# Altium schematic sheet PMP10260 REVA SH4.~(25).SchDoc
size 431 x 279 mm; Date: Not shown in title block; ApprovedBy: Not shown in title block; CheckedBy: Not shown in title block; Author: Not shown in title block; CompanyName: Not shown in title block; Engineer: Not shown in title block; Organization: Not shown in title block; Address1: Not shown in title block; Address2: Not shown in title block; Address3: Not shown in title block; Address4: Not shown in title block; DocumentNumber: 4; Revision: Use project parameter SCH_Rev; SheetNumber: 4; SheetTotal: 4; PageSetup: Record=PageOptions|CenterHorizontal=True|CenterVertical=True|PrintScale=1.00|XCorrection=1.00|YCorrection=1.00|PrintKind=0|BorderSize=5000000|LeftOffset=0|BottomOffset=0|Orientation=2|PaperLength=1000|PaperWidth=1000|Scale=100|PaperSource=15|PrintQuality=600|MediaType=1|DitherType=10|PaperKind=Letter|PrintScaleMode=1
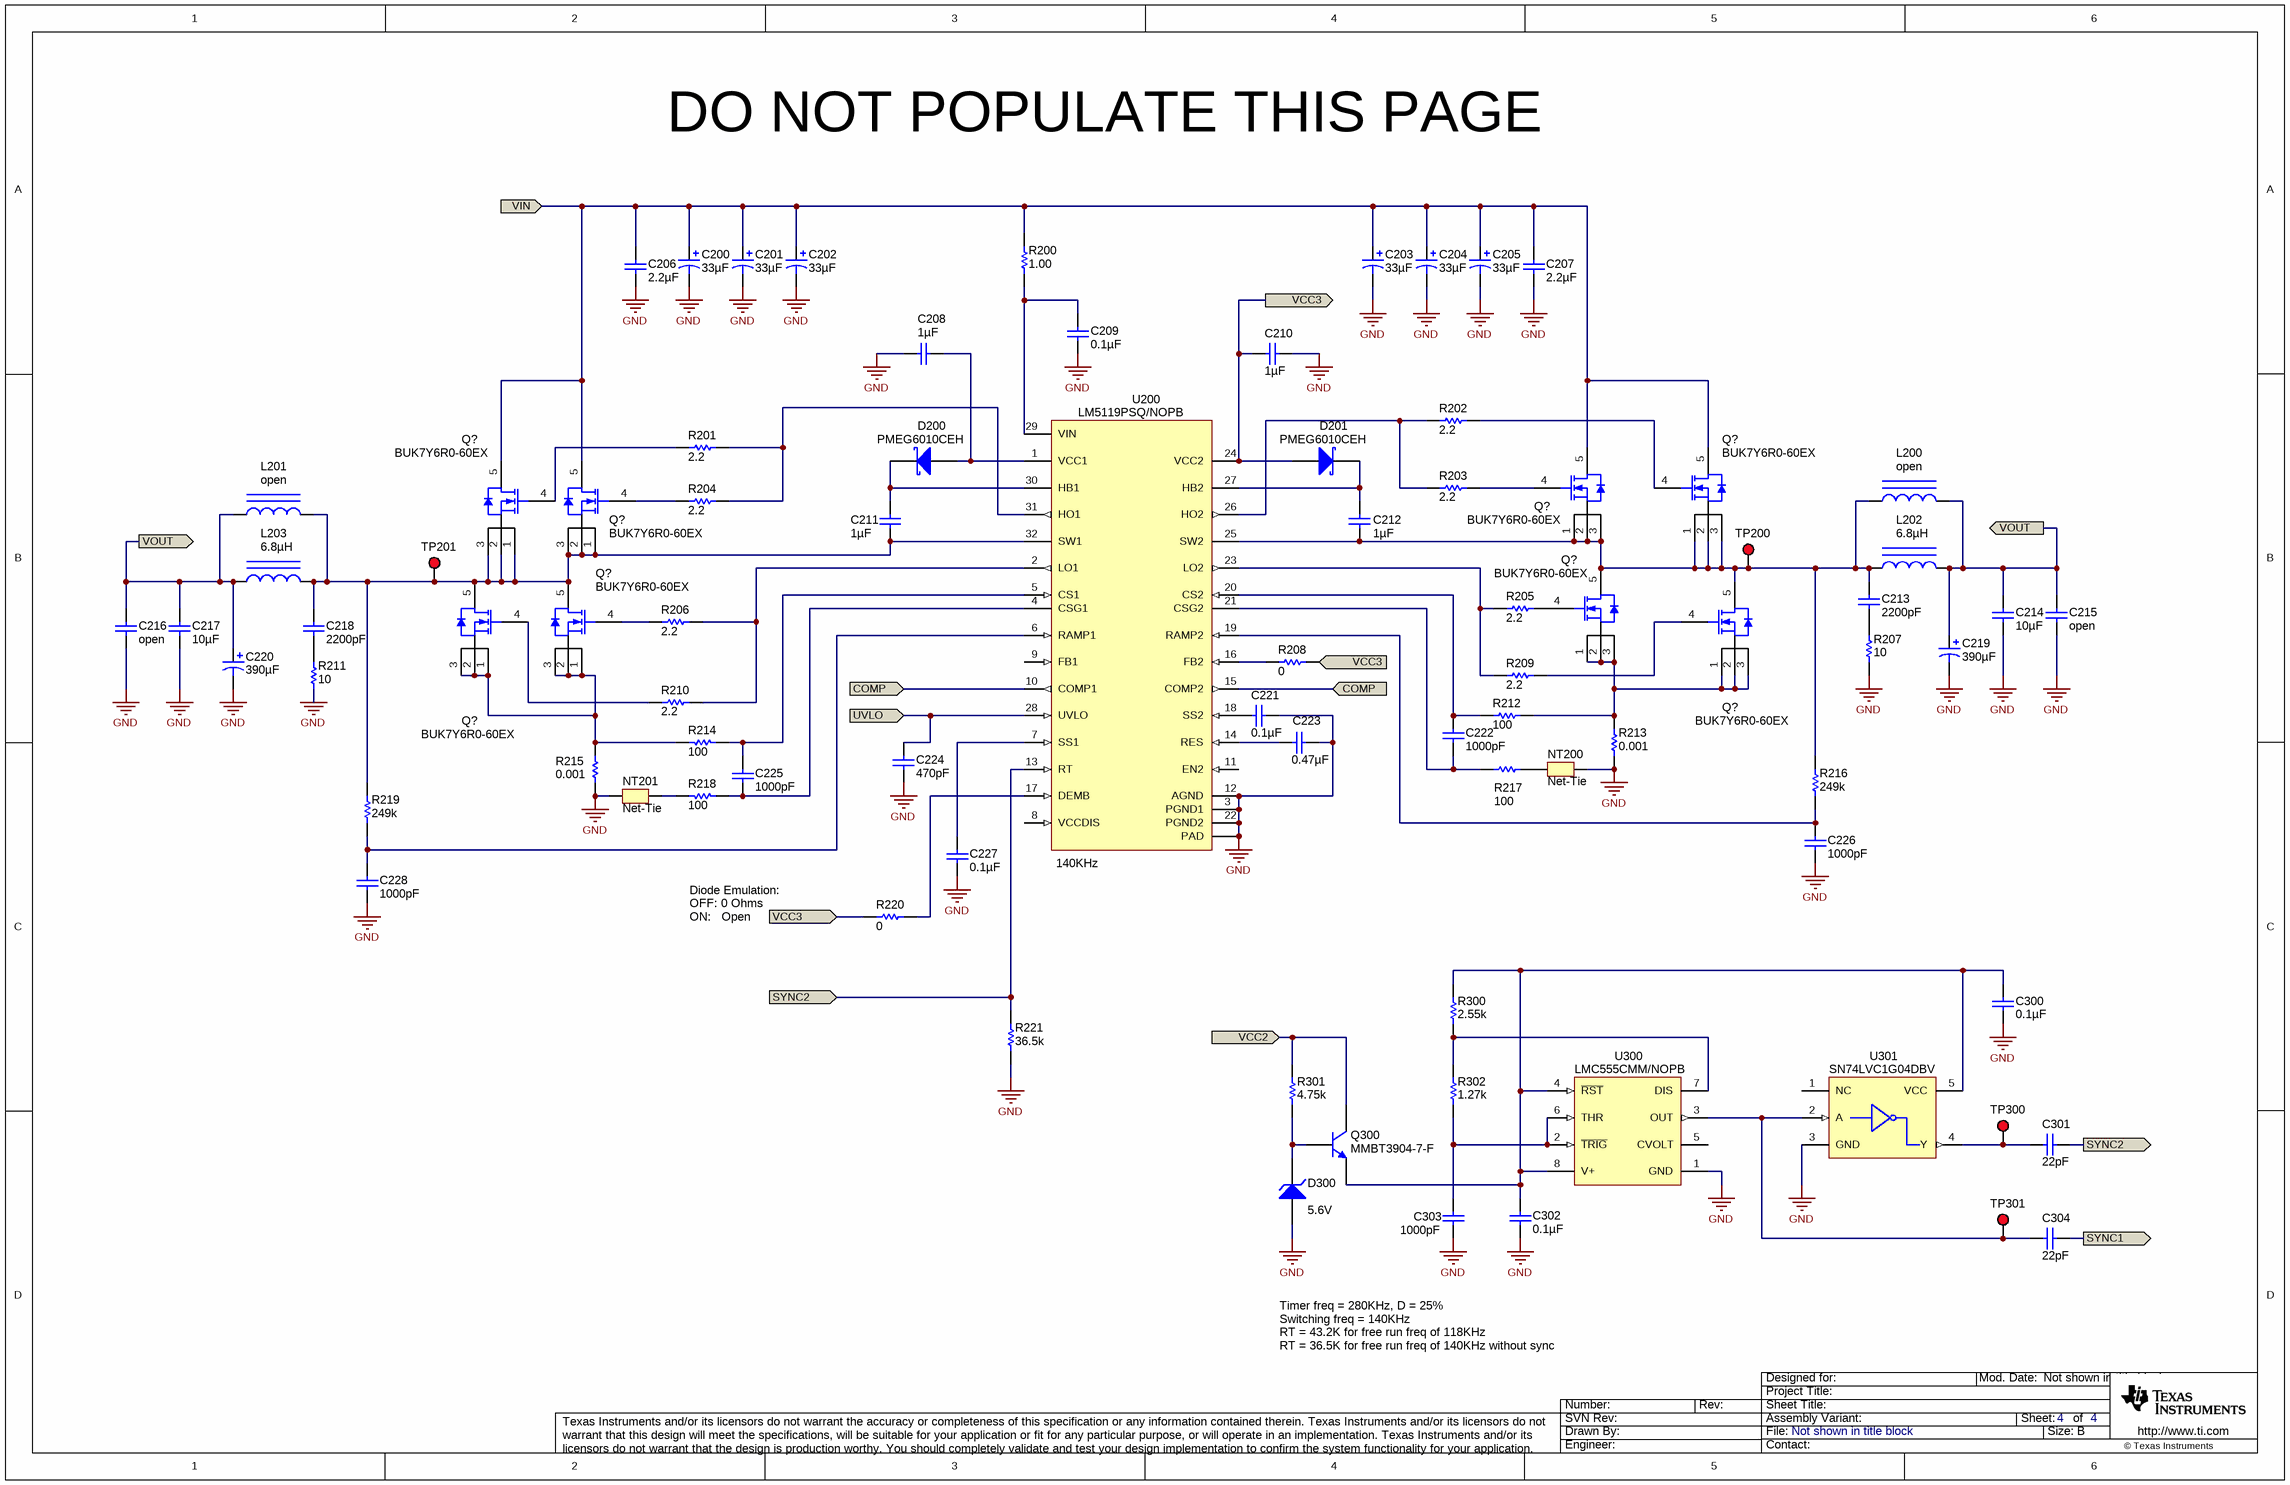
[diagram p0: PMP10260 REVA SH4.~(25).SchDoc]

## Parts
(Parts that share a designator on the sheet are numbered #1, #2 ... from top to bottom, then left to right.)
C200  ValueDisplayed: 33µF  [SXV_E12]  (hidden comment: 63SXV33M)
C201  ValueDisplayed: 33µF  [SXV_E12]  (hidden comment: 63SXV33M)
C202  ValueDisplayed: 33µF  [SXV_E12]  (hidden comment: 63SXV33M)
C203  ValueDisplayed: 33µF  [SXV_E12]  (hidden comment: 63SXV33M)
C204  ValueDisplayed: 33µF  [SXV_E12]  (hidden comment: 63SXV33M)
C205  ValueDisplayed: 33µF  [SXV_E12]  (hidden comment: 63SXV33M)
C206  ValueDisplayed: 2.2µF  [1210]  (hidden comment: GRM32ER72A225KA35L)
C207  ValueDisplayed: 2.2µF  [1210]  (hidden comment: GRM32ER72A225KA35L)
C208  ValueDisplayed: 1µF  [0603L]  (hidden comment: C1608X7R1E105K080AB)
C209  ValueDisplayed: 0.1µF  [0805_HV]  (hidden comment: C2012X7R2A104K)
C210  ValueDisplayed: 1µF  [0603L]  (hidden comment: C1608X7R1E105K080AB)
C211  ValueDisplayed: 1µF  [0603L]  (hidden comment: C1608X7R1E105K080AB)
C212  ValueDisplayed: 1µF  [0603L]  (hidden comment: C1608X7R1E105K080AB)
C213  ValueDisplayed: 2200pF  [0603L]  (hidden comment: C0603C222K5RAC)
C214  ValueDisplayed: 10µF  [1210L]  (hidden comment: GMK325AB7106MM-T)
C215  ValueDisplayed: open  [1210]
C216  ValueDisplayed: open  [1210]
C217  ValueDisplayed: 10µF  [1210L]  (hidden comment: GMK325AB7106MM-T)
C218  ValueDisplayed: 2200pF  [0603L]  (hidden comment: C0603C222K5RAC)
C219  ValueDisplayed: 390µF  [SM_RADIAL_8MM]  (hidden comment: 20SVPF390M)
C220  ValueDisplayed: 390µF  [SM_RADIAL_8MM]  (hidden comment: 20SVPF390M)
C221  ValueDisplayed: 0.1µF  [0603L]  (hidden comment: C1608X7R1H104K)
C222  ValueDisplayed: 1000pF  [0603]  (hidden comment: C1608C0G1H102J)
C223  ValueDisplayed: 0.47µF  [0603L]  (hidden comment: C0603C474K4RACTU)
C224  ValueDisplayed: 470pF  [0603]  (hidden comment: C1608C0G1H471J)
C225  ValueDisplayed: 1000pF  [0603]  (hidden comment: C1608C0G1H102J)
C226  ValueDisplayed: 1000pF  [0603]  (hidden comment: C1608C0G1H102J)
C227  ValueDisplayed: 0.1µF  [0603L]  (hidden comment: C1608X7R1H104K)
C228  ValueDisplayed: 1000pF  [0603]  (hidden comment: C1608C0G1H102J)
C300  ValueDisplayed: 0.1µF  [0805_HV]  (hidden comment: C2012X7R2A104K)
C301  ValueDisplayed: 22pF  [0603]  (hidden comment: C1608C0G1H220J)
C302  ValueDisplayed: 0.1µF  [0805_HV]  (hidden comment: C2012X7R2A104K)
C303  ValueDisplayed: 1000pF  [0603]  (hidden comment: C1608C0G1H102J)
C304  ValueDisplayed: 22pF  [0603]  (hidden comment: C1608C0G1H220J)
D200  PMEG6010CEH  [SOD-123F]
D201  PMEG6010CEH  [SOD-123F]
D300  value 5.6V  [SOD-123]  (hidden comment: MMSZ5232B-7-F)
L200  ValueDisplayed: open  [XAL1510]
L201  ValueDisplayed: open  [XAL1510]
L202  ValueDisplayed: 6.8µH  [SER2915]  (hidden comment: SER2915H-682KL)
L203  ValueDisplayed: 6.8µH  [SER2915]  (hidden comment: SER2915H-682KL)
NT200  Net-Tie  [Net-Tie_10mil]  (net tie, no BOM)
NT201  Net-Tie  [Net-Tie_10mil]  (net tie, no BOM)
Q300  MMBT3904-7-F  [SOT-23]
Q?#1  BUK7Y6R0-60EX  [LFPAK56]
Q?#2  BUK7Y6R0-60EX  [LFPAK56]
Q?#3  BUK7Y6R0-60EX  [LFPAK56]
Q?#4  BUK7Y6R0-60EX  [LFPAK56]
Q?#5  BUK7Y6R0-60EX  [LFPAK56]
Q?#6  BUK7Y6R0-60EX  [LFPAK56]
Q?#7  BUK7Y6R0-60EX  [LFPAK56]
Q?#8  BUK7Y6R0-60EX  [LFPAK56]
R200  value 1.00  [0805_HV]  (hidden comment: CRCW08051R00FKEA)
R201  value 2.2  [0603L]  (hidden comment: CRCW06032R20JNEA)
R202  value 2.2  [0603L]  (hidden comment: CRCW06032R20JNEA)
R203  value 2.2  [0603L]  (hidden comment: CRCW06032R20JNEA)
R204  value 2.2  [0603L]  (hidden comment: CRCW06032R20JNEA)
R205  value 2.2  [0603L]  (hidden comment: CRCW06032R20JNEA)
R206  value 2.2  [0603L]  (hidden comment: CRCW06032R20JNEA)
R207  value 10  [2010M]  (hidden comment: CRCW201010R0JNEFHP)
R208  value 0  [0603L]  (hidden comment: CRCW06030000Z0EA)
R209  value 2.2  [0603L]  (hidden comment: CRCW06032R20JNEA)
R210  value 2.2  [0603L]  (hidden comment: CRCW06032R20JNEA)
R211  value 10  [2010M]  (hidden comment: CRCW201010R0JNEFHP)
R212  value 100  [0603L]  (hidden comment: RC0603FR-07100RL)
R213  value 0.001  [2512M]  (hidden comment: ERJ-M1WTF1M0U)
R214  value 100  [0603L]  (hidden comment: RC0603FR-07100RL)
R215  value 0.001  [2512M]  (hidden comment: ERJ-M1WTF1M0U)
R216  value 249k  [0603]  (hidden comment: CRCW0603249KFKEA)
R217  value 100  [0603L]  (hidden comment: RC0603FR-07100RL)
R218  value 100  [0603L]  (hidden comment: RC0603FR-07100RL)
R219  value 249k  [0603]  (hidden comment: CRCW0603249KFKEA)
R220  value 0  [0603L]  (hidden comment: CRCW06030000Z0EA)
R221  value 36.5k  [0603]  (hidden comment: CRCW060336K5FKEA)
R300  value 2.55k  [0603]  (hidden comment: CRCW06032K55FKEA)
R301  value 4.75k  [0603]  (hidden comment: CRCW06034K75FKEA)
R302  value 1.27k  [0603]  (hidden comment: CRCW06031K27FKEA)
TP200  5010  [Keystone5010]  (value not drawn)
TP201  5010  [Keystone5010]  (value not drawn)
TP300  5010  [Keystone5010]  (value not drawn)
TP301  5010  [Keystone5010]  (value not drawn)
U200  LM5119PSQ/NOPB  [RTV0032A]
U300  LMC555CMM/NOPB  [MUA08A_N]
U301  SN74LVC1G04DBV  [DBV0005A_N]

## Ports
COMP, SYNC1, SYNC2, UVLO, VCC2, VCC3, VIN, VOUT

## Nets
GND: C200.2(-) C201.2(-) C202.2(-) C203.2(-) C204.2(-) C205.2(-) C206.2 C207.2 C208.2 C209.2 C210.2 C214.2 C215.2 C216.2 C217.2 C219.2(-) C220.2(-) C221.1 C223.1 C224.2 C226.2 C227.2 C228.2 C300.2 C302.2 C303.2 D300.2(A) NT200.2 NT201.1 R207.1 R211.1 R213.1 R215.1 R221.1 U200.3(PGND1) U200.12(AGND) U200.22(PGND2) U200.33(PAD) U300.1(GND) U301.3(GND)
COMP: U200.10(COMP1) U200.15(COMP2) ; port COMP
SYNC1: C304.1 ; port SYNC1
SYNC2: C301.1 R221.2 U200.13(RT) ; port SYNC2
UVLO: C224.1 U200.28(UVLO) ; port UVLO
VCC2: Q300.3(C) R301.2 ; port VCC2
VCC3: C210.1 D201.2(A) R208.2 R220.1 U200.24(VCC2) ; port VCC3
VIN: C200.1(+) C201.1(+) C202.1(+) C203.1(+) C204.1(+) C205.1(+) C206.1 C207.1 Q?#1.5(D) Q?#2.5(D) Q?#3.5(D) Q?#4.5(D) R200.1 ; port VIN
VOUT: C214.1 C215.1 C216.1 C217.1 C219.1(+) C220.1(+) L200.2 L201.1 L202.2 L203.1 ; port VOUT
NetC208_1: C208.1 D200.2(A) U200.1(VCC1)
NetC209_1: C209.1 R200.2 U200.29(VIN)
NetC211_1: C211.1 D200.1(K) U200.30(HB1)
NetC211_2: C211.2 C218.1 L201.2 L203.2 Q?#3.1(S) Q?#3.2(S) Q?#3.3(S) Q?#4.1(S) Q?#4.2(S) Q?#4.3(S) Q?#6.5(D) Q?#7.5(D) R219.2 TP201.1 U200.32(SW1)
NetC212_1: C212.1 D201.1(K) U200.27(HB2)
NetC212_2: C212.2 C213.1 L200.1 L202.1 Q?#1.1(S) Q?#1.2(S) Q?#1.3(S) Q?#2.1(S) Q?#2.2(S) Q?#2.3(S) Q?#5.5(D) Q?#8.5(D) R216.2 TP200.1 U200.25(SW2)
NetC213_2: C213.2 R207.2
NetC218_2: C218.2 R211.2
NetC221_2: C221.2 U200.18(SS2)
NetC222_1: C222.1 R212.1 U200.20(CS2)
NetC222_2: C222.2 R217.1 U200.21(CSG2)
NetC223_2: C223.2 U200.14(RES)
NetC225_1: C225.1 R214.1 U200.5(CS1)
NetC225_2: C225.2 R218.1 U200.4(CSG1)
NetC226_1: C226.1 R216.1 U200.19(RAMP2)
NetC227_1: C227.1 U200.7(SS1)
NetC228_1: C228.1 R219.1 U200.6(RAMP1)
NetC300_1: C300.1 C302.1 Q300.2(E) R300.2 U300.4(~{RST}) U300.8(V+) U301.5(VCC)
NetC301_2: C301.2 TP300.1 U301.4(Y)
NetC303_1: C303.1 R302.1 U300.2(~{TRIG}) U300.6(THR)
NetC304_2: C304.2 TP301.1 U300.3(OUT) U301.2(A)
NetD300_1: D300.1(K) Q300.1(B) R301.1
NetNT200_1: NT200.1 R217.2
NetNT201_2: NT201.2 R218.2
NetQ?#1_4: Q?#1.4(G) R203.2
NetQ?#2_4: Q?#2.4(G) R202.2
NetQ?#3_4: Q?#3.4(G) R201.1
NetQ?#4_4: Q?#4.4(G) R204.1
NetQ?#5_1: Q?#5.1(S) Q?#5.2(S) Q?#5.3(S) Q?#8.1(S) Q?#8.2(S) Q?#8.3(S) R212.2 R213.2
NetQ?#5_4: Q?#5.4(G) R205.2
NetQ?#6_1: Q?#6.1(S) Q?#6.2(S) Q?#6.3(S) Q?#7.1(S) Q?#7.2(S) Q?#7.3(S) R214.2 R215.2
NetQ?#6_4: Q?#6.4(G) R210.1
NetQ?#7_4: Q?#7.4(G) R206.1
NetQ?#8_4: Q?#8.4(G) R209.2
NetR201_2: R201.2 R204.2 U200.31(HO1)
NetR202_1: R202.1 R203.1 U200.26(HO2)
NetR205_1: R205.1 R209.1 U200.23(LO2)
NetR206_2: R206.2 R210.2 U200.2(LO1)
NetR208_1: R208.1 U200.16(FB2)
NetR220_2: R220.2 U200.17(DEMB)
NetR300_1: R300.1 R302.2 U300.7(DIS)

Not connected (* = marked no-connect by the designer): U200 8(VCCDIS) 9(FB1) 11(EN2); U300 5(CVOLT); U301 1(NC)

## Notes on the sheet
- DO NOT POPULATE THIS PAGE
- Diode Emulation:
- OFF: 0 Ohms
- (near U200) 140KHz
- ON:   Open
- Timer freq = 280KHz, D = 25%
- Switching freq = 140KHz
- RT = 43.2K for free run freq of 118KHz
- RT = 36.5K for free run freq of 140KHz without sync

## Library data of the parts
C200-C205 = 63SXV33M: CAP, OS-CON, 33uF, 63V, +/-20%, 0.025 ohm, 8.0x11.9mm SMD; Manufacturer: Panasonic; Polarized: Y; CompType: Capacitor; U/M: EA; Cap_F: 0.000033; Tolerance_%: 20; VDC_V: 63; ESR_Ohm: 0.025; IRMS_A: 2.95; TaMin_C: -55; TaMax_C: 105
C206 C207 = GRM32ER72A225KA35L: CAP, CERM, 2.2uF, 100V, +/-10%, X7R, 1210; Manufacturer: MuRata; Polarized: N; CompType: Capacitor; U/M: EA; Cap_F: 0.0000022; Tolerance_%: 10; ESR_Ohm: 0.007; Value1: 0.007 ohm; VDC_V: 100; IRMS_A: 4.4; TaMin_C: -55; TaMax_C: 125
C208 C210-C212 = C1608X7R1E105K080AB: CAP, CERM, 1uF, 25V, +/-10%, X7R, 0603; Manufacturer: TDK; Polarized: N; CompType: Capacitor; U/M: EA; Cap_F: 0.000001; Tolerance_%: 10; Value1: Unknown; VDC_V: 25; TaMin_C: -55; TaMax_C: 125; Cap_Case: 0603
C209 C300 C302 = C2012X7R2A104K: CAP, CERM, 0.1uF, 100V, +/-10%, X7R, 0805; Manufacturer: TDK; Polarized: N; CompType: Capacitor; U/M: EA; Cap_F: 0.0000001; Tolerance_%: 10; ESR_Ohm: 0.0158; Value1: 0.0158 ohm; VDC_V: 100; TaMin_C: -55; TaMax_C: 125; Cap_Case: 0805
C213 C218 = C0603C222K5RAC: CAP, CERM, 2200pF, 50V, +/-10%, X7R, 0603; Manufacturer: Kemet; Polarized: N; CompType: Capacitor; U/M: EA; Cap_F: 0.0000000022; Tolerance_%: 10; Value1: Unknown; VDC_V: 50; TaMin_C: -55; TaMax_C: 125; Cap_Case: 0603
C214 C217 = GMK325AB7106MM-T: CAP, CERM, 10uF, 35V, +/-20%, X7R, 1206; Manufacturer: Taiyo Yuden; Polarized: N; CompType: Capacitor; U/M: EA; Cap_F: 0.00001; Tolerance_%: 20; Value1: Unknown; VDC_V: 35; TaMin_C: -55; TaMax_C: 125; Cap_Case: 1210
C215 C216 = C3225X7R1H335M: CAP, CERM, open, 1210; Manufacturer: TDK; Polarized: N; CompType: Capacitor; Value: 10uF; U/M: EA; Cap_F: 0.0000033; Tolerance_%: 20; Value1: Unknown; VDC_V: 50; Value2: 50V; TempCo: X5R; TaMin_C: -55; TaMax_C: 125
C219 C220 = 20SVP100M: CAP, OS-CON, 390uF, 20V, +/-20%, 0.014 ohm, 8x10 SMD; Manufacturer: Sanyo; Polarized: Y; CompType: Capacitor; U/M: EA; Cap_F: 0.0001; Tolerance_%: 20; ESR_Ohm: 0.024; IRMS_A: 3.32; TaMin_C: -55; TaMax_C: 105; Cap_Case: 8.3x8.3x11.9
C221 C227 = C1608X7R1H104K: CAP, CERM, 0.1uF, 50V, +/-10%, X7R, 0603; Manufacturer: TDK; Polarized: N; CompType: Capacitor; U/M: EA; Cap_F: 0.0000001; Tolerance_%: 10; ESR_Ohm: 0.017; Value1: 0.017 ohm; VDC_V: 50; TaMin_C: -55; TaMax_C: 125; Cap_Case: 0603
C222 C225 C226 C228 C303 = C1608C0G1H102J: CAP, CERM, 1000pF, 50V, +/-5%, C0G/NP0, 0603; Manufacturer: TDK; Polarized: N; CompType: Capacitor; U/M: EA; Cap_F: 0.000000001; Tolerance_%: 5; ESR_Ohm: 0.0563; Value1: 0.0563 ohm; VDC_V: 50; TaMin_C: -55; TaMax_C: 125
C223 = C0603C474K4RACTU: CAP, CERM, 0.47uF, 16V, +/-10%, X7R, 0603; Manufacturer: Kemet; Polarized: N; CompType: Capacitor; U/M: EA; Cap_F: 0.00000047; Tolerance_%: 10; Value1: Unknown; VDC_V: 16; TaMin_C: -55; TaMax_C: 125; Cap_Case: 0603
C224 = C1608C0G1H471J: CAP, CERM, 470pF, 50V, +/-5%, C0G/NP0, 0603; Manufacturer: TDK; Polarized: N; CompType: Capacitor; U/M: EA; Cap_F: 0.00000000047; Tolerance_%: 5; ESR_Ohm: 0.0922; Value1: 0.0922 ohm; VDC_V: 50; TaMin_C: -55; TaMax_C: 125
C301 C304 = C1608C0G1H220J: CAP, CERM, 22pF, 50V, +/-5%, C0G/NP0, 0603; Manufacturer: TDK; Polarized: N; CompType: Capacitor; U/M: EA; Cap_F: 0.000000000022; Tolerance_%: 5; ESR_Ohm: 0.3882; Value1: 0.3882 ohm; VDC_V: 50; TaMin_C: -55; TaMax_C: 125
D200 D201 = PMEG6010CEH,115: Diode, Schottky, 60V, 1A, SOD-123F; Manufacturer: NXP Semiconductor; U/M: EA; Vf_V: 0.57; Value2: 0.57V; Io_A: 1; Vr_V: 60; TJmax_C: 150
D300 = MMSZ5232B-7-F: Diode, Zener, 5.6V, 500mW, SOD-123; Manufacturer: Diodes Inc.; SymbolCreator: a0412235; U/M: EA; Power_W: 0.5; Vz_V: 5.6; Value1: 0.5W; RJA_CperW: 350
L200 L201 = XAL1510-682MEB: Inductor, Shielded, Composite, 6.8uH, 26A, 0.00417 ohm, SMD; Ind_H: 6.8E-6; Imax_A: 26; Irms: 26A @ 40C rise; Isat: 36A @ 30% inductance drop; U/M: EA
L202 L203 = SER2915H-682KL: Inductor, Shielded E Core, Ferrite, 6.8uH, 30A, 0.00186 ohm, SMD; Manufacturer: Coilcraft; Ind_H: 6.8E-6; Imax_A: 30; Irms: 30A @ 40C rise; Isat: 36.2A @ 30% inductance drop; U/M: EA
NT200 NT201 = Net-Tie: Single point connection between nets.; SymbolCreator: codlsc
Q300 = MMBT3904-7-F, Diodes Inc.: Transistor, NPN, 40V, 0.2A, SOT-23; CompType: BJT; PNP: 0; NPN: 1; Vceo_V: 40; Vcesat1_V: 0.2; Value: 0.2V; HfeMax: 400; TaMin_C: -55; TaMax_C: 150; U/M: EA
Q?#1-Q?#8 = BUK7Y6R0-60EX: MOSFET, N-CH, 60V, 100A, SOT669; Manufacturer: NXP Semiconductor; Alternate Manufacturer: None; SymbolCreator: a0412235; U/M: EA; ChType: N; VdsMax_V: 60; Value1: ? ohm; Value2: 45.4 nC; QgTyp_nC: 45.4; Vgs_V: 20; IdsMax_A: 100
R200 = CRCW08051R00FKEA: RES, 1.00 ohm, 1%, 0.125W, 0805; Manufacturer: Vishay-Dale; CompType: Resistor; Res_ohm: 1; Value_Code: 1R00; Power_W: 0.125; VDC_V: 150; TempCo: 100 ppm/C; EIA_Code: E96; U/M: EA
R201-R206 R209 R210 = CRCW06032R20JNEA: RES, 2.2 ohm, 5%, 0.1W, 0603; Manufacturer: Vishay-Dale; CompType: Resistor; Value_Code: 2R20; Tolerance_%: 5; Power_W: 0.1; VDC_V: 75; TempCo: 200 ppm/C; EIA_Code: E24; U/M: EA
R207 R211 = CRCW20101R00JNEFHP: RES, 10 ohm, 5%, 1W, 2010; Manufacturer: Vishay-Dale; CompType: Resistor; Res_ohm: 1; Value_Code: 1R00; Tolerance_%: 5; VDC_V: 400; TempCo: 200 ppm/C; EIA_Code: E24; U/M: EA
R208 R220 = CRCW06030000Z0EA: RES, 0 ohm, 5%, 0.1W, 0603; Manufacturer: Vishay-Dale; CompType: Resistor; Value_Code: 0000; Tolerance_%: 5; Power_W: 0.1; VDC_V: 75; TempCo: 200 ppm/C; EIA_Code: E24; U/M: EA
R212 R214 R217 R218 = RC0603FR-07100RL: RES, 100 ohm, 1%, 0.1W, 0603; Manufacturer: Yageo America; CompType: Resistor; Value_Code: 100R; Tolerance_%: 1; Power_W: 0.1; VDC_V: 150; TempCo: 200 ppm/C; EIA_Code: E96; U/M: EA
R213 R215 = ERJ-M1WTF1M0U: RES, 0.001 ohm, 1%, 1W, 2512; Manufacturer: Panasonic; CompType: Resistor; Value_Code: R001; Tolerance_%: 1; TempCo: ppm/C; EIA_Code: E96; U/M: EA
R216 R219 = CRCW0603249KFKEA: RES, 249k ohm, 1%, 0.1W, 0603; Manufacturer: Vishay-Dale; CompType: Resistor; Res_ohm: 249000; Tolerance_%: 1; Power_W: 0.1; VDC_V: 75; TempCo: 100 ppm/C; EIA_Code: E96; U/M: EA
R221 = CRCW060336K5FKEA: RES, 36.5k ohm, 1%, 0.1W, 0603; Manufacturer: Vishay-Dale; CompType: Resistor; Res_ohm: 36500; Value_Code: 36k5; Tolerance_%: 1; Power_W: 0.1; VDC_V: 75; TempCo: 100 ppm/C; EIA_Code: E96; U/M: EA
R300 = CRCW06032K55FKEA: RES, 2.55k ohm, 1%, 0.1W, 0603; Manufacturer: Vishay-Dale; CompType: Resistor; Res_ohm: 2550; Value_Code: 2k55; Tolerance_%: 1; Power_W: 0.1; VDC_V: 75; TempCo: 100 ppm/C; EIA_Code: E96; U/M: EA
R301 = CRCW06034K75FKEA: RES, 4.75k ohm, 1%, 0.1W, 0603; Manufacturer: Vishay-Dale; CompType: Resistor; Res_ohm: 4750; Value_Code: 4k75; Tolerance_%: 1; Power_W: 0.1; VDC_V: 75; TempCo: 100 ppm/C; EIA_Code: E96; U/M: EA
R302 = CRCW06031K27FKEA: RES, 1.27k ohm, 1%, 0.1W, 0603; Manufacturer: Vishay-Dale; CompType: Resistor; Res_ohm: 1270; Value_Code: 1k27; Tolerance_%: 1; Power_W: 0.1; VDC_V: 75; TempCo: 100 ppm/C; EIA_Code: E96; U/M: EA
TP200 TP201 TP300 TP301 = 5010: Test Point, Multipurpose, Red, TH; Manufacturer: Keystone; CompType: Test Point Loop; U/M: EA
U200 = LM5119PSQ/NOPB: LM5119/LM5119Q Wide Input Range Dual Synchronous Buck Controller, RTV0032A; Alternate Manufacturer: None; Manufacturer: Texas Instruments; SymbolCreator: a0411947; CompType: IC; U/M: EA
U300 = LMC555CMM/NOPB: CMOS Timer, 8-pin Mini SOIC, Pb-Free; Manufacturer: National Semiconductor; PackageTopMarking: ZXTT*ZC5; PowerWise: N; CompType: Analog IC
U301 = SN74LVC1G04DBV: Single Inverter Gate, DBV0005A; Alternate Manufacturer: None; Manufacturer: Texas Instruments; SymbolCreator: a0411947; CompType: IC; U/M: EA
